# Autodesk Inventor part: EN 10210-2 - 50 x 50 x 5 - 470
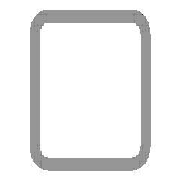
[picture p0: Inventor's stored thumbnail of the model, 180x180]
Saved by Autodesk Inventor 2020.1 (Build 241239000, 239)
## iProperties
_CCFamilyMember: 16
_CCFamilyDisplayName: DIN EN 10210-2 (USAS B17.1 quadratisch) - Rohrleitung — In Klammern angegebene Größen wurden aufgehoben
_FrameMemberDoc: Frame Member File
_Version: 15.0.0
_GetPNFromCC: 1
IsCustomPart: 1
Created: 2019-10
Part Number: EN 10210-2 - 50 x 50 x 5 - 470
Material: Stahl, weich
Description: Rohrleitung
Document SubType Name: Modeling
Standard: DIN
Designer: lutzd
Standard Revision: 2006-07
Standards Organization: DIN
Language: de-DE
Size Designation: 50 x 50 x 5
Categories: <MemberInstance><Categories><Category DisplayName="Profile" InternalName="089c4875-fa83-4c05-b084-43b9cc11f5ed" Mnemonic="GRDR"><CategoryParameter DisplayName="
Stock Number: 50 x 50 x 5
Mass: 3221.58 g
Surface Area: 1608.6 cm^2
Volume: 410.392 cm^3
Density: 7.85 g/cm^3
Appearance: Halbpoliert
G_L: 470,000 mm
G_W: 50,000 mm
G_H: 50,000 mm
Dimensions: 50x50x470 mm
Mass: 3,222 kg
DocNumber: ADSK-014093
Folder: .
+39FD1857-A883-47ED-9B21-31CA88832428+SCHNITTDETAIL1: Schnittwinkel 90,00 grd
Title: Profil-Bauteil
Author: lutzd
Revision Number: -
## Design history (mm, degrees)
node "Startebene"
node "Endebene"
sketch "Skizze"
  geometry: L1 (-25, -17.5)-(-25, 17.5); L2 (-17.5, 25)-(17.5, 25); L3 (25, 17.5)-(25, -17.5); L4 (17.5, -25)-(-17.5, -25); L5 (-15, 20)-(15, 20); L6 (20, 15)-(20, -15); L7 (15, -20)-(-15, -20); L8 (-20, -15)-(-20, 15); L9 (0, 37.175)-(0, -37.175) reference; L10 (-37.175, 0)-(37.175, 0) reference; A1 r 7.5 centre (-17.5, -17.5) between (-25, -17.5) and (-17.5, -25); A2 r 7.5 centre (-17.5, 17.5) between (-17.5, 25) and (-25, 17.5); A3 r 7.5 centre (17.5, 17.5) between (25, 17.5) and (17.5, 25); A4 r 7.5 centre (17.5, -17.5) between (17.5, -25) and (25, -17.5); A5 r 5 centre (-15, -15) between (-20, -15) and (-15, -20); A6 r 5 centre (-15, 15) between (-15, 20) and (-20, 15); A7 r 5 centre (15, 15) between (20, 15) and (15, 20); A8 r 5 centre (15, -15) between (15, -20) and (20, -15)
  constraints: 16 end point, 16 point on circle, 16 tangent, 8 centre point, 6 equal radius, 4 parallel, 2 perpendicular, 2 other
  dimensions: "d7" = 7.5 radius of A1 (= G_IR); "d10" = 50 distance between parallel lines of L2 L4 (= G_H); "d11" = 50 distance between parallel lines of L1 L3 (= G_W); "d12" = 5 distance between parallel lines of L3 L6 (= G_T); "d15" = 25 distance between parallel lines of L2 L10 (= 0.5 x d10); "d16" = 25 distance between parallel lines of L9 L3 (= 0.5 x d11); "d19" = 5 radius of A5 (= G_T); "d20" = 5 distance between parallel lines of L4 L7 (= G_T)
extrude "Körper" new body sketch "Skizze" stored distance "d3" = 470 (= G_L); taper "d4" = 0 deg
node "Driven Length"
  sketch "Sketch3"
    geometry: L1 (0, 0)-(10, 0) reference
    constraints: 2 end point, 1 horizontal
  workplane "Work Plane3"
  sketch "Sketch4"
    geometry: L1 (-2, 50)-(12, 50) reference; L2 (-2, 520)-(12, 520) reference
    dimensions: "d18" = 470 distance between parallel lines of L1 L2 (derived)
workplane "Arbeitsebene4"
feature "Trennen1"
body "Solid1"
other parameters: "G_W" = 50 [user parameter; used in 1 equation term], "G_H" = 50 [user parameter; used in 1 equation term], "G_T" = 5 [user parameter; used in 3 equation terms], "G_IR" = 7.5 [user parameter; used in 1 equation term], "G_L" = 470 (= d18) [user parameter; used in 1 equation term], "G_OFFSET_END" = 0 [user parameter; used in 1 equation term], "d17" = 90 deg
